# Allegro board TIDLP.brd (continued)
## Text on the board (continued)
Ref Des/Silkscreen Top: BALLAST | PB_DONGLE | 1 | 10 | SM_PIC | INT_SENS | LED_EN | I2C_0 | JTAG_BS | SPI_CTRL | LMP_HOT | I2C_1 | MAN_RST | I2C_2 | D_BLK | 3D_TOG | ADC_SENS | CWI2 | CW2_MD | DMD_P3P3V | CWI1 | CW1_MD | FO | FAN4 | FAN1 | FAN2 | FAN5 | FAN3 | FAN6 | 5VFAN | LP_BYP | FID3 | RS-232_0 | L2F_SENS | PWM_DRV | SPI_DRV | DSP_PWM_DRV | FID1 | DSP_RST | I2C_CLK | I2C_DA | HOLD_BL | KEY_PD | RS-232_1 | TEST_I/F | A | FRONTEND_I/F | FE_P1P2V | COMP_SENS | DSP_P1P8V | FAN6_EN | FID2 | ASSY 2512026  REV[ ] | SCH 2512024  REV[ ] | PCB 2512025  REV[ ] | MSN [     ] | TIDLP-20465-02 | TEXAS INSTRUMENTS | SILKSCREEN - PRIMARY SIDE | 9    12
LY2GND: LAYER 2 - GND PLANE | 2    12
LY3: LAYER 3 - SIGNAL | 3    12
LY4: LAYER 4 - SIGNAL | 4    12
LY5PWR: LAYER 5 - PWR PLANE | 5    12
DISPLAY_TOP: SOLDERPASTE - PRIMARY SIDE | 11    12
PASTEMASK_BOTTOM: SOLDERPASTE - SECONDARY SIDE | 12    12
User.8: 0 | PRIMARY SIDE VIEW | FABRICATION DRAWING | 6 | 1    1 | LAYER STACK: | A MINIMUM OF 150 MICROINCHES ELECTROLYTIC NICKEL. | 2. APPLY LPI SOLDERMASK. | COLOR: GREEN. | CONFORM TO IPC-SM-840, CLASS H. CURRENT REV. | SOLDERMASK SHALL BE COMPATIBLE WITH SAC305 OR | EQUIVALENT SOLDER ALLOY AND SOLDER FLOAT BATH | TEMPERATURE OF 288 C. | 6  PLATE INDICATED PAD AREAS, SECONDARY SIDE, | WITH A MINIMUM OF 35, MAXIMUM 50 MICROINCHES ELECTROLYTIC | HARD GOLD OVER A MINIMUM OF 100, MAXIMUM 200 MICROINCHES OF | ELECTROLYTIC NICKEL. | LAYER 1 - PRIMARY SIDE - 0.5oz START - 50 OHMS +/-10% - .007 WIDTH | LAYER 2 - GND PLANE - 2oz | LAYER 3 - SIGNAL - 1oz - 50 OHMS +/-10% - .00675 WIDTH | LAYER 4 - SIGNAL - 1oz - 50 OHMS +/-10% - .00675 WIDTH | LAYER 5 - SPLIT PWR PLANE - 2oz | LAYER 6 - SECONDARY SIDE - 0.5oz START - 50 OHMS +/-10% - .007 WIDTH | ADJUST DIELECTRIC THICKNESS TO MEET SPECIFIED IMPEDENCE | .028 | .006 | .005 | DIFFERENTIAL 100 OHMS +/-10% - .004125 WIDTH/.00588 SPACE | DIFFERENTIAL 100 OHMS +/-10% - .00425 WIDTH/.00475 SPACE | SOLDERMASK SHALL | 4. APPLY LPI SILKSCREEN OR EQUIVALENT PER THE ARTWORK. | COLOR: WHITE.
User.20: FIGURE | SIZE | 9.0 | 12.0 | 16.0 | 20.0 | 28.0 | 35.0 | 36.0 | 38.0 | 40.0 | 42.0 | 45.0 | 50.0 | 90.0 | 120.0 | 157.0 | 25.98 | 60.0 | 66.0 | 74.0 | 92.5 | 94.0 | 182.0 | DRILL CHART: TOP to BOTTOM | ALL UNITS ARE IN MILS | TOLERANCE | +3.0/-9.0 | +3.0/-12.0 | +3.0/-3.0 | +2.0/-2.0 | PLATED | NON-PLATED | QTY | 581 | 2110 | 48 | 14 | 72 | 5 | 4 | 36 | 81 | 20 | 6 | 10 | 2 | 1
